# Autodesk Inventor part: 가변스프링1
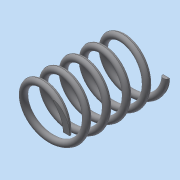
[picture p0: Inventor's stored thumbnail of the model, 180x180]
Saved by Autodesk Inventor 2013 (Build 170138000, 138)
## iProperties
Created: 2018-10
Part Number: 가변스프링1
Material: 일반
Document SubType Name: Modeling
Designer: Administrator
Density: 1 g/cm^3
Mass: 0.780491 g
Surface Area: 15.7949 cm^2
Volume: 0.780491 cm^3
Author: Administrator
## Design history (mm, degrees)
sketch "스케치1"
  geometry: L1 (0, 0)-(0, 30.255); L2 (0, 30.255)-(8, 30.255); L3 (0, 0)-(8, 0); C1 r 1 at (8, 0)
  constraints: 6 end point, 1 centre point, 1 coincident, 1 parallel, 1 perpendicular, 1 vertical
  dimensions: "d0" = 30.25501 distance of L1.start L1.end (derived); "d1" = 8 distance of L1.end L2.end; "d3" = 2 diameter of C1; "d4" = 16 diameter of L3.end L1
feature "코일1" sketch "스케치1" pitch "d5" = 10; turns "d7" = 5; dims "d6" = 30.25501 (= d0), "d8" = 0, angle "d9" = 90 deg, angle "d10" = 90 deg, "d11" = 0, "d12" = 0
sketch "스케치2"
  geometry: L1 (30.255, 10)-(0, 10); L2 (0, 10)-(0, -10); L3 (0, -10)-(30.255, -10); L4 (30.255, -10)-(30.255, 10); 2 further points
  constraints: 8 end point, 2 parallel, 1 coincident, 1 horizontal, 1 midpoint, 1 perpendicular
  dimensions: "d13" = 30.25501 distance of L2.end L3.end (derived); "d15" = 20 distance between parallel lines of L3 L1
extrude "돌출1" sketch "스케치2" stored distance "d16" = 0; taper "d17" = 0 deg
node "솔리드1"
